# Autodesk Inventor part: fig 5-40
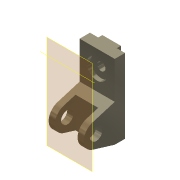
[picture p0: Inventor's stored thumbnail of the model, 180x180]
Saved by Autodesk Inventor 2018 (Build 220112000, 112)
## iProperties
Shininess: 65.0
Angle Display Precision: 2
Document Length Units: 11269
Document Angle Units: 11279
Document Time Units: 11290
Document Mass Units: 11283
Document Length Units Precision: 3
Document Angle Units Precision: 2
Created: 2001-11
Part Number: fig 5-40
Document SubType Name: Modeling
Designer: Renu Muthoo
Density: 1 g/cm^3
Material: Generic
Appearance: Metal-Titanium (Polished)
Density: 0.0
Volumn: 0.0
Area: 0.0
PropertySet Name: Model Information
Control State: 0
Master: False
Checked Out: False
Author: Renu Muthoo
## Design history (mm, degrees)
node "Sketch1"
sketch "Sketch2"
  geometry: L1 (33.257, 104.664)-(33.257, -75.336); L2 (33.257, -75.336)-(8.257, -75.336); L3 (8.257, -75.336)-(-45.451, -59.045); L4 (-45.451, -1.628)-(8.257, 14.664); L5 (8.257, 14.664)-(8.257, 104.664); L6 (8.257, 104.664)-(33.257, 104.664); C1 r 15 at (-36.743, -30.336); A1 r 30 centre (-36.743, -30.336) between (-45.451, -1.628) and (-45.451, -59.045)
  constraints: 12 end point, 2 centre point, 2 equal length, 2 parallel, 2 point on circle, 2 tangent, 1 coincident, 1 perpendicular, 1 vertical
  dimensions: "d0" = 180 distance of L1.start L1.end; "d1" = 30 radius of A1; "d2" = 25 distance of L5.end L1.start; "d3" = 45 distance from line of L2 A1.centre; "d4" = 70 distance from line of L1 A1.centre; "d5" = 30 diameter of C1
extrude "Extrusion1" new body sketch "Sketch2" distance "d6" = 85; taper "d7" = 0 deg
workplane "Work Plane1"
sketch "Sketch3"
  geometry: L1 (15, 62.364)-(70, 62.364); L2 (70, 62.364)-(70, -52.386); L3 (70, -52.386)-(15, -52.386); L4 (15, -52.386)-(15, 62.364); L5 (0, -45)-(0, -28.708) reference
  constraints: 8 end point, 2 parallel, 1 horizontal, 1 perpendicular
  dimensions: "d8" = 55 distance of L1.start L1.end; "d9" = 15 distance between parallel lines of L5 L4
extrude "Extrusion2" cut sketch "Sketch3" distance "d10" = 50; taper "d11" = 0 deg
sketch "Sketch4"
  geometry: L1 (0, 25)-(85, 25) reference; L2 (0, 0)-(0, 25) reference; L3 (20, 25)-(65, 25); L4 (65, 25)-(65, 35); L5 (65, 35)-(20, 35); L6 (20, 35)-(20, 25)
  constraints: 8 end point, 2 parallel, 1 horizontal, 1 perpendicular, 1 point on line
  dimensions: "d12" = 45 distance of L4.end L5.end; "d13" = 10 distance of L3.end L4.end; "d14" = 20 distance between parallel lines of L2 L6
extrude "Extrusion3" join sketch "Sketch4" stored distance "d15" = 50; taper "d16" = 0 deg
sketch "Sketch5"
  geometry: L1 (85, 0)-(85, 90) reference; L2 (0, 90)-(85, 90) reference; 1 further point
  dimensions: "d17" = 42 distance from line of L2 point (42.5, 48); "d18" = 42.5 distance from line of L1 point (42.5, 48)
hole "Hole1" sketch "Sketch5" at (42.5, 48) diameter "d19" = 20; stored, may be unused: countersink angle "d23" = 82 deg, drill point angle "d25" = 118 deg; dims "d20" = 6, "d21" = 50, "d22" = 10, "d24" = 8
workaxis "Work Axis1"
  workplane "Work Plane3"
body "Solid1"
